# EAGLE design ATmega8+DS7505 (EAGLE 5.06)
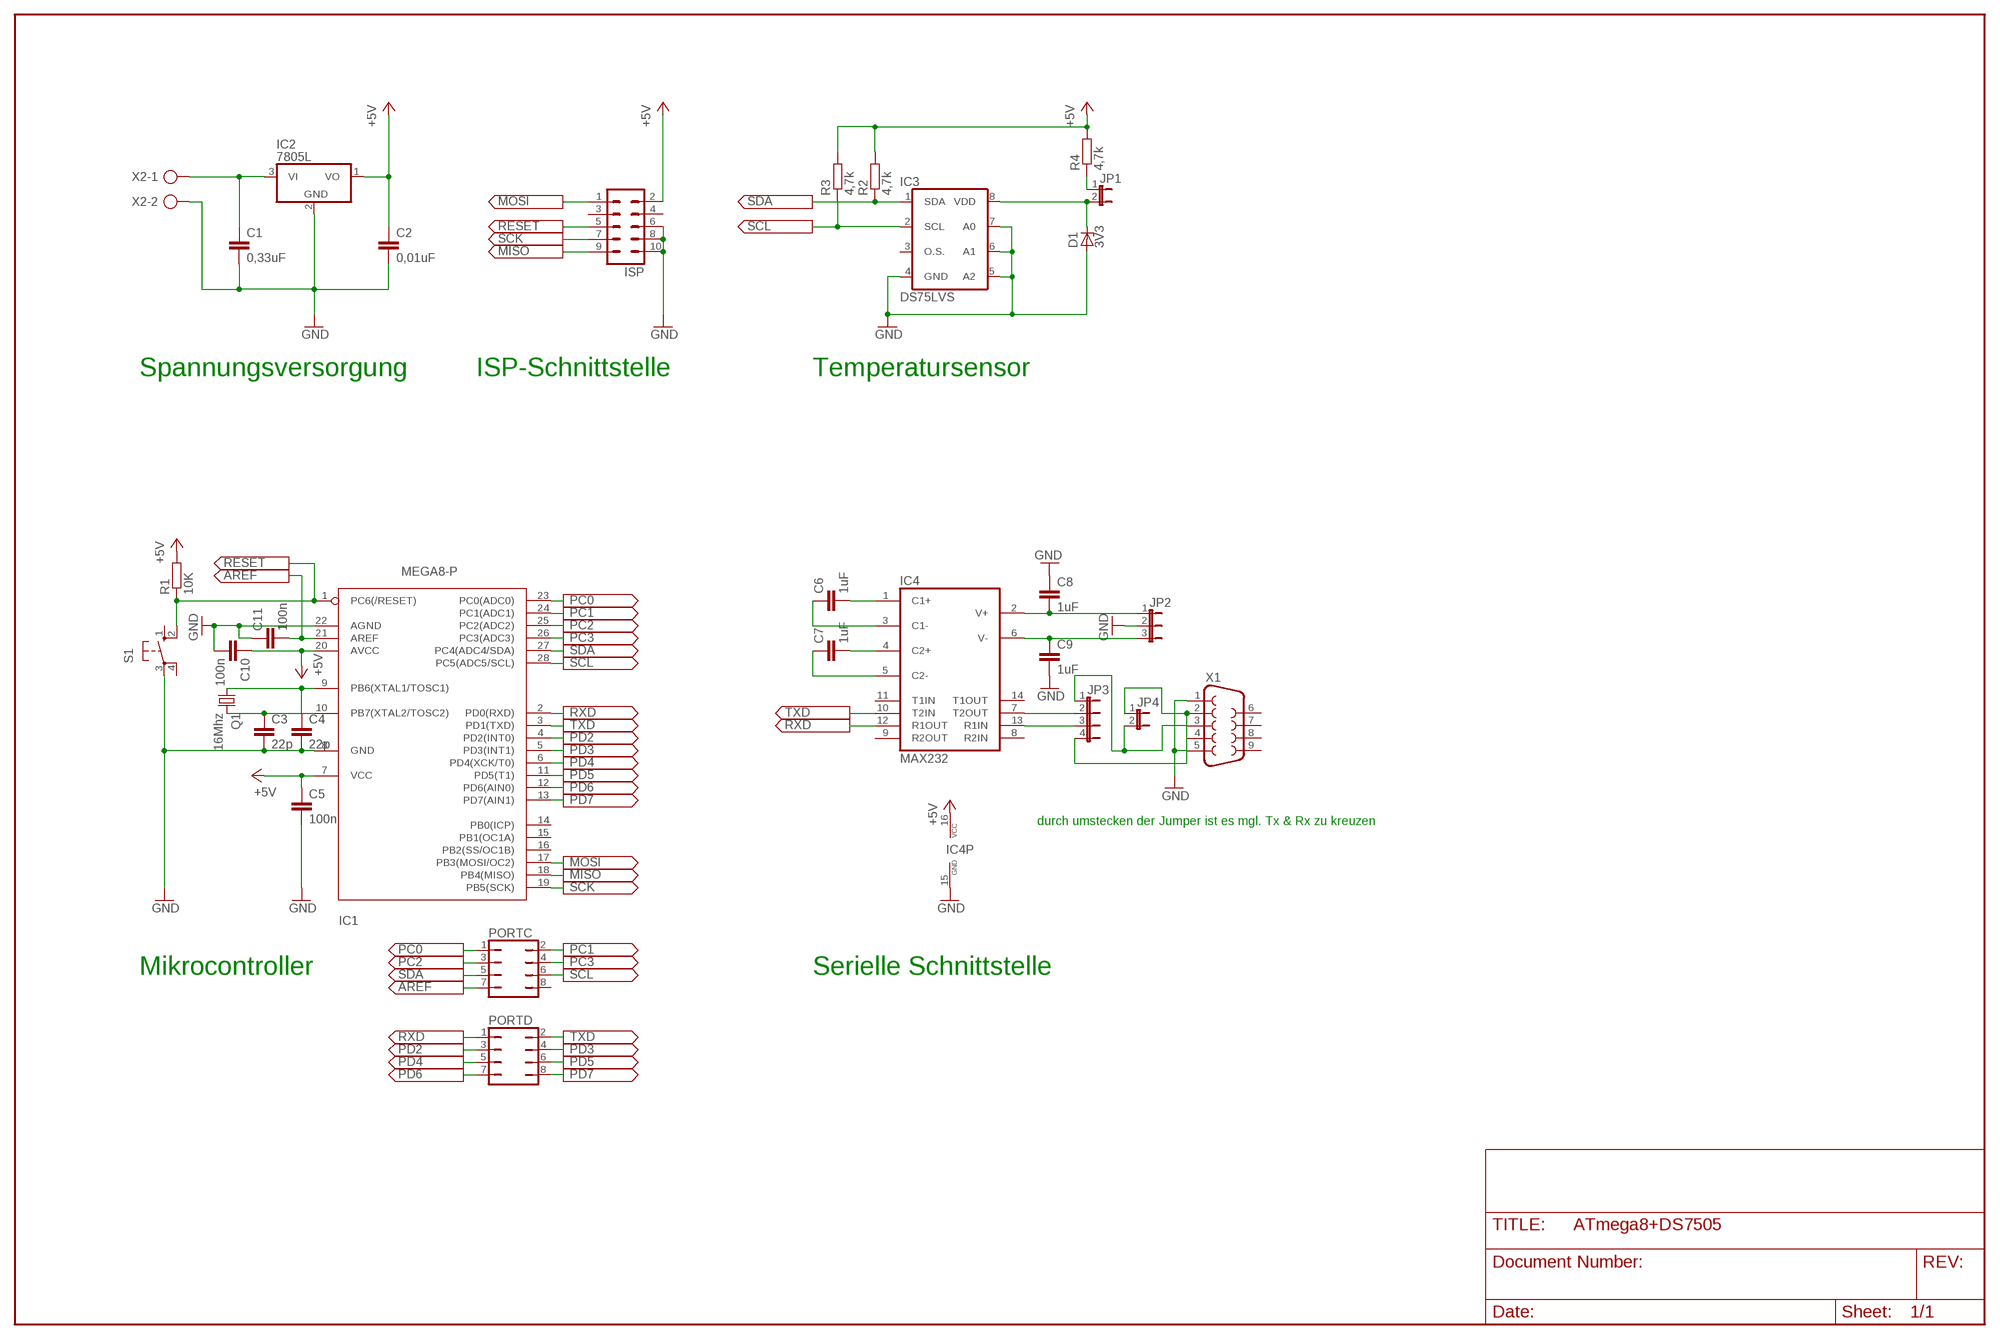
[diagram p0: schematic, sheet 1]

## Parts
C1  0,33uF  C-EU050-025X075  [C050-025X075]
C2  0,01uF  C-EU050-025X075  [C050-025X075]
C3  22p  C-EU050-025X075  [C050-025X075]
C4  22p  C-EU050-025X075  [C050-025X075]
C5  100n  C-EU050-025X075  [C050-025X075]
C6  1uF  C-EU050-025X075  [C050-025X075]
C7  1uF  C-EU050-025X075  [C050-025X075]
C8  1uF  C-EU050-025X075  [C050-025X075]
C9  1uF  C-EU050-025X075  [C050-025X075]
C10  100n  C-EU050-025X075  [C050-025X075]
C11  100n  C-EU050-025X075  [C050-025X075]
D1  3V3  ZENER-DIODEDO34-7  [DO34Z7]
IC1  MEGA8-P  [DIL28-3]
IC2  7805L  [TO92]
IC3  DS75LVS  [SO08]
IC4  MAX232  [DIL16]
ISP  MA05-2  [MA05-2]
JP1  JP1E  [JP1]
JP2  JP2E  [JP2]
JP3  JP4E  [JP4]
JP4  JP1E  [JP1]
PORTC  JP4Q  [JP4Q]
PORTD  JP4Q  [JP4Q]
Q1  16Mhz  CRYSTALHC49S  [HC49/S]
R1  10K  R-EU_0204/7  [0204/7]
R2  4,7k  R-EU_0204/7  [0204/7]
R3  4,7k  R-EU_0204/7  [0204/7]
R4  4,7k  R-EU_0204/7  [0204/7]
S1  10-XX  [B3F-10XX]
X1  F09H  [F09H]
X2  AK300/2  [AK300/2]

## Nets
+5V: C2.1 C5.1 C10.1 IC1.7(VCC) IC1.20(AVCC) IC2.1(VO) IC4.16(VCC) ISP.2 R1.2 R2.2 R3.2 R4.2
AREF: C11.2 IC1.21(AREF) PORTC.7
GND: C1.2 C2.2 C3.2 C4.2 C5.2 C8.1 C9.2 C10.2 C11.1 D1.A IC1.8(GND) IC1.22(AGND) IC2.2(GND) IC3.4(GND) IC3.5(A2) IC3.6(A1) IC3.7(A0) IC4.15(GND) ISP.6 ISP.8 ISP.10 JP2.2 S1.3(P) X1.1 X1.5 X2.2
MISO: IC1.18(PB4(MISO)) ISP.9
MOSI: IC1.17(PB3(MOSI/OC2)) ISP.1
N$1: C1.1 IC2.3(VI) X2.1
N$2: JP1.1 R4.1
N$3: C4.1 IC1.9(PB6(XTAL1/TOSC1)) Q1.1
N$4: C3.1 IC1.10(PB7(XTAL2/TOSC2)) Q1.2
N$6: JP3.4 JP4.1 X1.2
N$7: IC4.7(T2OUT) JP3.2
N$8: IC4.13(R1IN) JP3.3
N$9: C6.2 IC4.1(C1+)
N$10: C6.1 IC4.3(C1-)
N$11: C7.2 IC4.4(C2+)
N$12: C7.1 IC4.5(C2-)
N$13: C9.1 IC4.6(V-) JP2.3
N$14: C8.2 IC4.2(V+) JP2.1
N$15: D1.C IC3.8(VDD) JP1.2
N$17: JP3.1 JP4.2 X1.3
PC0: IC1.23(PC0(ADC0)) PORTC.1
PC1: IC1.24(PC1(ADC1)) PORTC.2
PC2: IC1.25(PC2(ADC2)) PORTC.3
PC3: IC1.26(PC3(ADC3)) PORTC.4
PD2: IC1.4(PD2(INT0)) PORTD.3
PD3: IC1.5(PD3(INT1)) PORTD.4
PD4: IC1.6(PD4(XCK/T0)) PORTD.5
PD5: IC1.11(PD5(T1)) PORTD.6
PD6: IC1.12(PD6(AIN0)) PORTD.7
PD7: IC1.13(PD7(AIN1)) PORTD.8
RESET: IC1.1(PC6(/RESET)) ISP.5 R1.1 S1.2(S1)
RXD: IC1.2(PD0(RXD)) IC4.12(R1OUT) PORTD.1
SCK: IC1.19(PB5(SCK)) ISP.7
SCL: IC1.28(PC5(ADC5/SCL)) IC3.2(SCL) PORTC.6 R3.1
SDA: IC1.27(PC4(ADC4/SDA)) IC3.1(SDA) PORTC.5 R2.1
TXD: IC1.3(PD1(TXD)) IC4.10(T2IN) PORTD.2
Unconnected: IC1.14(PB0(ICP)) IC1.15(PB1(OC1A)) IC1.16(PB2(SS/OC1B)) IC3.3(O.S.) IC4.8(R2IN) IC4.9(R2OUT) IC4.11(T1IN) IC4.14(T1OUT) ISP.3 ISP.4 PORTC.8 S1.1(S) S1.4(P1) X1.4 X1.6 X1.7 X1.8 X1.9

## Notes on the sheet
- Spannungsversorgung | ISP-Schnittstelle | Temperatursensor
- durch umstecken der Jumper ist es mgl. Tx & Rx zu kreuzen
- Mikrocontroller | Serielle Schnittstelle

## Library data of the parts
C1-C11 = rcl:C-EU: CAPACITOR, European symbol
D1 = diode:ZENER-DIODE: Z-Diode
IC1 = atmel:MEGA8-P: MICROCONTROLLER 8 Kbytes FLASH 1 kbytes SRAM 512 bytes EEPROM USART 4-channel 10 bit ADC 2-channel 8 bit ADC Source: avr.lbr
IC2 = linear:78*: Positive VOLTAGE REGULATOR Source: http://cache.national.com/ds/LM/LM78L05.pdf http://www.fairchildsemi.com/ds/LM/LM7805.pdf
IC3 = DS75LV:DS75LV: low-voltage (1.7V to 3.7V) digital thermometer and thermostat
IC4 = maxim:MAX232: RS232 TRANSEIVER
ISP = con-lstb:MA05-2: PIN HEADER
JP1 JP4 = jumper:JP1E: JUMPER
JP2 = jumper:JP2E: JUMPER
JP3 = jumper:JP4E: JUMPER
PORTC PORTD = jumper:JP4Q: JUMPER
Q1 = crystal:CRYSTAL: CRYSTAL
R1-R4 = rcl:R-EU_: RESISTOR, European symbol
S1 = switch-omron:10-XX: OMRON SWITCH
X1 = con-subd:F09: SUB-D
X2 = con-ptr500:AK300/2: CONNECTOR

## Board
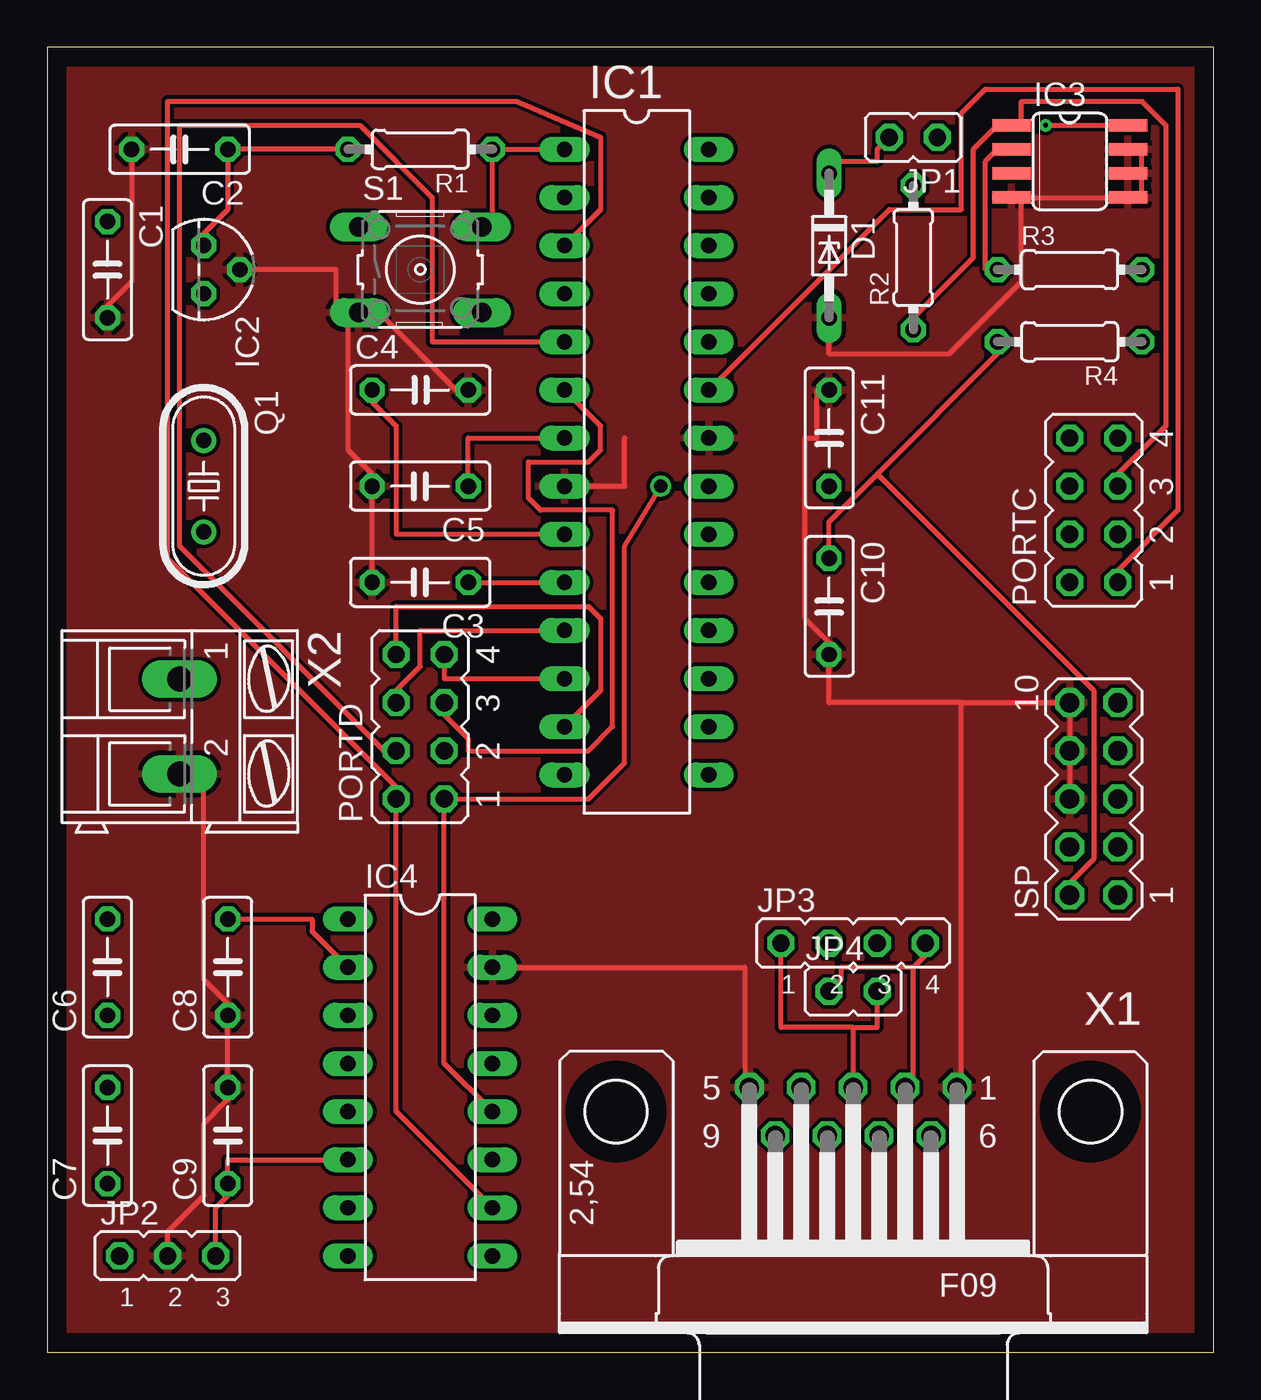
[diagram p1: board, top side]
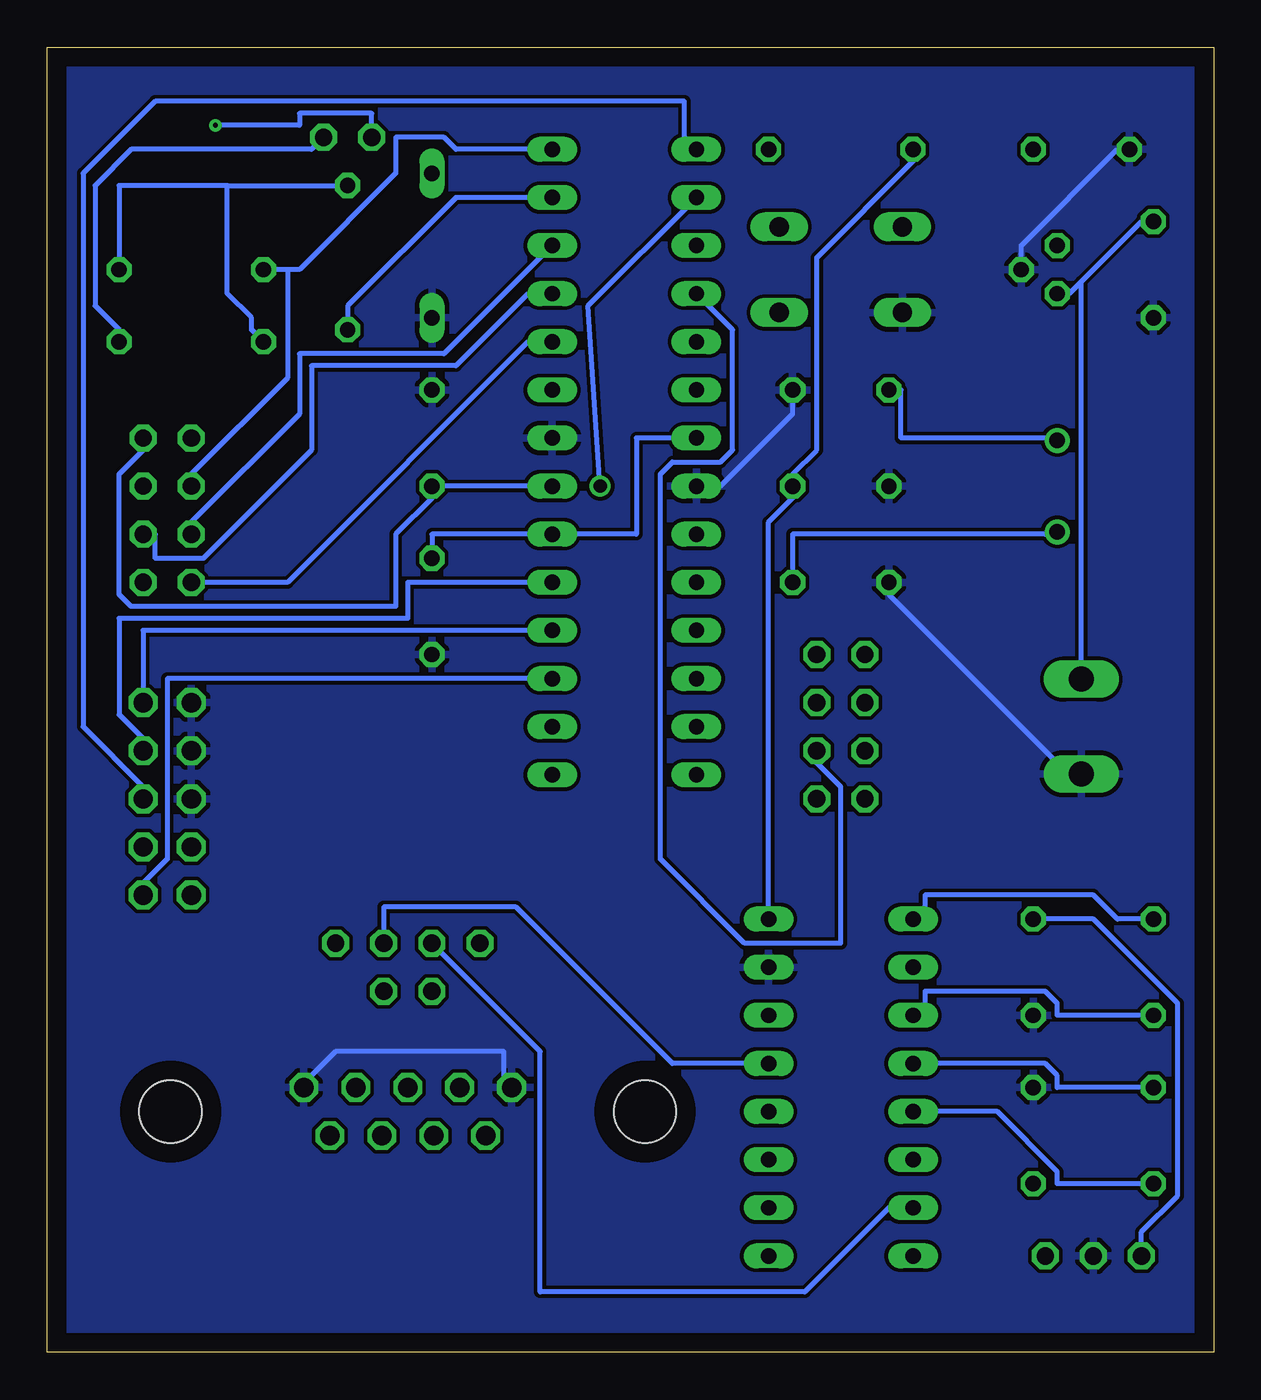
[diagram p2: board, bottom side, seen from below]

Size 61.58 x 68.89 mm. Coordinates in mm from the lower left corner, seen from the top.
Outline: 0,0 61.58,0 61.58,68.89 0,68.89 0,0
Copper layers (1*16): Top 0.035mm / dielectric 1.5mm / Bottom 0.035mm
Design rules "default *": minimum track width 10mil, minimum drill 10mil, track to track 8mil, track to pad 8mil, pad to pad 8mil, via to via 8mil, smd to smd 8mil, copper to edge 40mil, drill to drill 8mil, minimum pad ring 10mil, minimum via ring 8mil, stop-mask expansion 4mil, vias tented up to drill 0mil, thermal gap 10mil

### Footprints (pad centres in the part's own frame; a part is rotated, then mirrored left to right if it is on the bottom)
C050-025X075 = drill 0.813 octagon: 1 -2.54,0; 2 2.54,0
DO34Z7 = drill 0.813 long: A 3.81,0; C -3.81,0
DIL28-3 = drill 0.813 long: 1 -16.51,-3.81; 2 -13.97,-3.81; 3 -11.43,-3.81; 4 -8.89,-3.81; 5 -6.35,-3.81; 6 -3.81,-3.81; 7 -1.27,-3.81; 8 1.27,-3.81; 9 3.81,-3.81; 10 6.35,-3.81; 11 8.89,-3.81; 12 11.43,-3.81; 13 13.97,-3.81; 14 16.51,-3.81; 15 16.51,3.81; 16 13.97,3.81; 17 11.43,3.81; 18 8.89,3.81; 19 6.35,3.81; 20 3.81,3.81; 21 1.27,3.81; 22 -1.27,3.81; 23 -3.81,3.81; 24 -6.35,3.81; 25 -8.89,3.81; 26 -11.43,3.81; 27 -13.97,3.81; 28 -16.51,3.81
TO92 = drill 0.813 octagon: 1 -1.27,0; 2 0,1.905; 3 1.27,0
SO08 = smd 0.66 x 2.032: 1 -1.905,-3.073; 2 -0.635,-3.073; 3 0.635,-3.073; 4 1.905,-3.073; 5 1.905,3.073; 6 0.635,3.073; 7 -0.635,3.073; 8 -1.905,3.073
DIL16 = drill 0.813 long: 1 -8.89,-3.81; 2 -6.35,-3.81; 3 -3.81,-3.81; 4 -1.27,-3.81; 5 1.27,-3.81; 6 3.81,-3.81; 7 6.35,-3.81; 8 8.89,-3.81; 9 8.89,3.81; 10 6.35,3.81; 11 3.81,3.81; 12 1.27,3.81; 13 -1.27,3.81; 14 -3.81,3.81; 15 -6.35,3.81; 16 -8.89,3.81
MA05-2 = drill 1.016 octagon: 1 -5.08,-1.27; 2 -5.08,1.27; 3 -2.54,-1.27; 4 -2.54,1.27; 5 0,-1.27; 6 0,1.27; 7 2.54,-1.27; 8 2.54,1.27; 9 5.08,-1.27; 10 5.08,1.27
JP1 = drill 0.914 octagon: 1 0,-1.27; 2 0,1.27
JP2 = drill 0.914 octagon: 1 -2.54,0; 2 0,0; 3 2.54,0
JP4 = drill 0.914 octagon: 1 -3.81,0; 2 -1.27,0; 3 1.27,0; 4 3.81,0
JP4Q = drill 0.914 octagon: 1 -3.81,-1.27; 2 -3.81,1.27; 3 -1.27,-1.27; 4 -1.27,1.27; 5 1.27,-1.27; 6 1.27,1.27; 7 3.81,-1.27; 8 3.81,1.27
HC49/S = drill 0.813 round: 1 -2.413,0; 2 2.413,0
0204/7 = drill 0.813 octagon: 1 -3.81,0; 2 3.81,0
B3F-10XX = drill 1.016 long: 1 -3.251,2.261; 2 3.251,2.261; 3 -3.251,-2.261; 4 3.251,-2.261
F09H = drill 1.016 octagon: 1 -5.486,-1.27; 2 -2.743,-1.27; 3 0,-1.27; 4 2.743,-1.27; 5 5.486,-1.27; 6 -4.115,1.27; 7 -1.372,1.27; 8 1.372,1.27; 9 4.115,1.27 | hole 3.302: -12.522,0; 12.522,0
AK300/2 = drill 1.321 long: 1 -2.515,0; 2 2.489,0

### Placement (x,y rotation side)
C1  3.17,57.15 270 top
C2  6.99,63.5 180 top
C3  19.68,40.64 180 top
C4  19.68,50.8 0 top
C5  19.68,45.72 180 top
C6  3.17,20.32 90 top
C7  3.17,11.43 90 top
C8  9.53,20.32 90 top
C9  9.53,11.43 90 top
C10  41.27,39.37 270 top
C11  41.27,48.26 270 top
D1  41.27,58.42 270 top
IC1  31.11,46.99 270 top
IC2  8.26,57.15 270 top
IC3  53.98,62.87 270 top
IC4  19.68,13.97 270 top
ISP  55.24,29.21 90 top
JP1  45.72,64.14 90 top
JP2  6.35,5.08 0 top
JP3  42.55,21.59 0 top
JP4  42.55,19.05 270 top
PORTC  55.24,44.45 90 top
PORTD  19.68,33.02 90 top
Q1  8.26,45.72 270 top
R1  19.68,63.5 180 top
R2  45.72,57.78 90 top
R3  53.98,57.15 0 top
R4  53.98,53.34 180 top
S1  19.68,57.15 0 top
X1  42.55,12.7 180 top
X2  6.99,33.02 270 top

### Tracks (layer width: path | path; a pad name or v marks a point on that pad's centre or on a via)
+5V
  Top 0.254: 43.81,46.35 41.27,43.81 C10.1 | 43.81,46.35 50.16,52.7 R4.2 | 43.81,46.35 55.24,34.92 55.24,26.04 53.98,24.77 ISP.2 | IC2.1 8.26,59.05 9.53,60.33 C2.1 R1.2 | IC1.7 22.23,48.26 C5.1
  Bottom 0.254: C10.1 41.27,43.18 IC1.20 30.48,43.18 30.48,48.26 IC1.7 | IC4.16 23.5,43.81 22.23,45.09 C5.1 22.23,46.35 20.95,47.62 20.95,57.78 15.88,62.87 R1.2 | 52.07,61.59 57.78,61.59 R3.2 | 52.07,61.59 R2.2 | 52.07,61.59 52.07,55.88 50.8,54.61 50.8,53.98 R4.2
AREF
  Bottom 0.254: IC1.21 C11.2 41.27,45.09 43.18,43.18 43.18,39.37 57.15,39.37 57.78,40.01 57.78,46.35 56.52,47.62 PORTC.7
GND
  Top 0.254: JP2.2 6.35,6.35 8.26,8.26 8.26,12.06 9.53,13.34 C9.2 C8.1 9.53,18.41 8.26,19.68 8.26,29.84 X2.2 | C3.2 C5.2 17.14,46.35 15.88,47.62 15.88,54.61 S1.3 | C1.2 3.17,55.24 4.45,56.52 C2.2 | IC2.2 15.24,57.15 15.24,55.24 S1.3 | S1.3 17.78,54.61 21.59,50.8 C4.2 | IC4.15 36.83,20.32 36.83,14.61 X1.5 | 57.78,62.23 57.78,63.5 IC3.7 | 51.44,60.96 IC3.5 57.78,60.96 57.78,62.23 | 57.78,62.23 IC3.6 | ISP.6 ISP.8 ISP.10 48.26,34.29 | 40.64,50.8 40.64,48.26 40.01,48.26 40.01,38.73 41.27,37.47 C10.2 41.27,34.29 48.26,34.29 | D1.A 41.27,52.7 47.62,52.7 51.44,56.52 51.44,60.96 | 51.44,60.96 IC3.4 | 48.26,34.29 48.26,14.61 X1.1 | 30.48,48.26 30.48,45.72 IC1.8
  Bottom 0.254: X2.2 8.26,31.11 17.14,40.01 C3.2 | IC1.8 26.04,45.72 22.23,49.53 C4.2 | C2.2 5.08,63.5 10.16,58.42 IC2.2 | X1.1 47.62,14.61 46.35,15.88 37.47,15.88 37.47,14.61 X1.5
  pour Bottom: 0,68.58 61.59,68.58 61.59,0 0,0
  pour Top: 0,68.58 61.59,68.58 61.59,0 0,0
MISO
  Bottom 0.254: IC1.18 56.52,38.1 ISP.9
MOSI
  Bottom 0.254: IC1.17 55.24,35.56 55.24,26.04 56.52,24.77 ISP.1
N$1
  Bottom 0.254: 6.99,56.52 7.62,55.88 IC2.3 | 6.99,56.52 3.81,59.69 C1.1 | X2.1 6.99,56.52
N$2
  Bottom 0.254: R4.1 57.78,53.98 59.05,55.24 59.05,61.59 57.15,63.5 47.62,63.5 JP1.1
N$3
  Top 0.254: IC1.9 18.41,43.18 18.41,48.9 17.14,50.16 C4.1
  Bottom 0.254: Q1.1 8.89,48.26 16.51,48.26 16.51,50.8 C4.1
N$4
  Top 0.254: C3.1 IC1.10
  Bottom 0.254: Q1.2 8.89,43.18 22.23,43.18 C3.1
N$6
  Top 0.254: 45.09,13.97 X1.2 45.72,13.97 45.72,20.32 | 45.72,20.32 46.35,20.95 JP3.4 | JP4.1 41.91,19.68 41.91,20.32 45.72,20.32
N$7
  Bottom 0.254: IC4.7 17.14,7.62 21.59,3.17 35.56,3.17 35.56,15.88 JP3.2
N$8
  Bottom 0.254: IC4.13 28.57,15.24 36.83,23.5 43.81,23.5 JP3.3
N$9
  Bottom 0.254: C6.2 5.08,22.86 6.35,24.13 15.24,24.13 15.24,23.5 IC4.1
N$10
  Bottom 0.254: C6.1 8.26,17.78 8.26,18.41 8.89,19.05 15.24,19.05 15.24,18.41 IC4.3
N$11
  Bottom 0.254: C7.2 8.26,13.97 8.26,14.61 8.89,15.24 IC4.4
N$12
  Bottom 0.254: C7.1 8.26,8.89 8.26,9.53 11.43,12.7 IC4.5
N$13
  Top 0.254: JP2.3 8.89,7.62 9.53,8.26 C9.1 9.53,10.16 IC4.6
N$14
  Top 0.254: C8.2 13.97,22.86 13.97,22.23 IC4.2
  Bottom 0.254: JP2.1 3.81,6.35 1.91,8.26 1.91,18.41 6.35,22.86 C8.2
N$15  (via drill 0.25)
  Top 0.254: D1.C 41.91,62.87 43.81,62.87 43.81,63.5 JP1.2 | v52.7,64.77 IC3.8
  Bottom 0.254: v52.7,64.77 48.26,64.77 48.26,65.41 44.45,65.41 JP1.2
N$17
  Top 0.254: JP3.1 38.73,17.14 42.55,17.14 | 42.55,17.14 43.81,17.14 JP4.2 | X1.3 42.55,17.14
PC0
  Top 0.254: IC1.23 44.45,60.33 48.26,60.33 48.26,65.41 49.53,66.67 59.69,66.67 59.69,44.45 56.52,41.27 PORTC.1
PC1
  Bottom 0.254: IC1.24 36.2,53.34 48.9,40.64 PORTC.2
PC2
  Bottom 0.254: IC1.25 36.2,55.88 40.01,52.07 47.62,52.07 47.62,47.62 53.34,41.91 55.88,41.91 55.88,43.18 PORTC.3
PC3
  Bottom 0.254: IC1.26 40.64,52.7 48.26,52.7 48.26,49.53 53.98,43.81 PORTC.4
PD2
  Bottom 0.254: IC1.4 25.4,53.98 25.4,47.62 26.04,46.99 28.57,46.99 29.21,46.35 29.21,26.04 24.77,21.59 19.68,21.59 19.68,29.84 20.95,31.11 PORTD.3
PD3
  Top 0.254: IC1.5 20.32,53.34 20.32,60.96 16.51,64.77 6.99,64.77 6.99,42.55 17.78,31.75 PORTD.4
PD4
  Top 0.254: IC1.6 29.21,48.9 29.21,47.62 28.57,46.99 25.4,46.99 25.4,45.09 26.04,44.45 29.84,44.45 29.84,33.02 28.57,31.75 22.23,31.75 22.23,32.38 20.95,33.66 PORTD.5
PD5
  Top 0.254: IC1.11 19.68,38.1 19.68,36.2 18.41,34.92 PORTD.6
PD6
  Top 0.254: IC1.12 20.95,35.56 PORTD.7
PD7
  Top 0.254: IC1.13 29.21,34.92 29.21,38.73 28.57,39.37 18.41,39.37 PORTD.8
RESET
  Top 0.254: IC1.1 R1.1 23.5,59.69 S1.2
  Bottom 0.254: ISP.5 56.52,29.84 59.69,33.02 59.69,62.23 55.88,66.04 27.94,66.04 27.94,64.14 IC1.1
RXD  (via drill 0.7)
  Top 0.254: IC4.12 20.95,15.24 PORTD.1 28.57,29.21 30.48,31.11 30.48,42.55 v32.38,45.72
  Bottom 0.254: v32.38,45.72 33.02,55.24 IC1.2
SCK
  Bottom 0.254: IC1.19 42.55,40.64 42.55,38.73 57.78,38.73 57.78,33.66 56.52,32.38 ISP.7
SCL
  Top 0.254: IC3.2 50.16,63.5 49.53,62.87 49.53,57.15 R3.1
  Bottom 0.254: 48.9,57.15 48.26,57.15 43.18,62.23 43.18,64.14 40.64,64.14 40.01,63.5 IC1.28 | 48.9,57.15 R3.1 | 48.9,57.15 48.9,51.44 53.98,46.35 PORTC.6
SDA
  Top 0.254: R2.1 45.72,54.61 48.9,57.78 48.9,63.5 50.16,64.77 IC3.1 51.44,64.77 51.44,66.04 57.78,66.04 59.05,64.77 59.05,48.9 56.52,46.35 PORTC.5
  Bottom 0.254: IC1.27 40.01,60.96 45.72,55.24 R2.1
TXD
  Top 0.254: IC4.10 18.41,12.7 PORTD.2 18.41,29.84 6.35,41.91 6.35,66.04 24.77,66.04 29.21,64.14 29.21,60.33 IC1.3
